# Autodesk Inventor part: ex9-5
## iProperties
Author: Administrator
Created: 2001-09
Part Number: ex9-5
Document SubType Name: Sheet Metal
Designer: Administrator
Control State: 0
Master: False
Checked Out: False
PropertySet Name: Design Tracking Control
Length Units: 11272
Angle Units: 11279
Time Units: 11290
Mass Units: 11286
Shininess: 3
Angle Display Precision: 2
Document Length Units: 11272
Document Angle Units: 11286
Document Time Units: 11279
Document Mass Units: 11290
Document Length Units Precision: 3
Document Angle Units Precision: 2
Compacted: False
PropertySet Name: _Private Model Information
Density: 0.0
Volumn: 0.0
Area: 0.0
PropertySet Name: Model Information
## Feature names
1. Plate1
2. Bend1
3. Plate2
4. Bend2
5. Cut1
